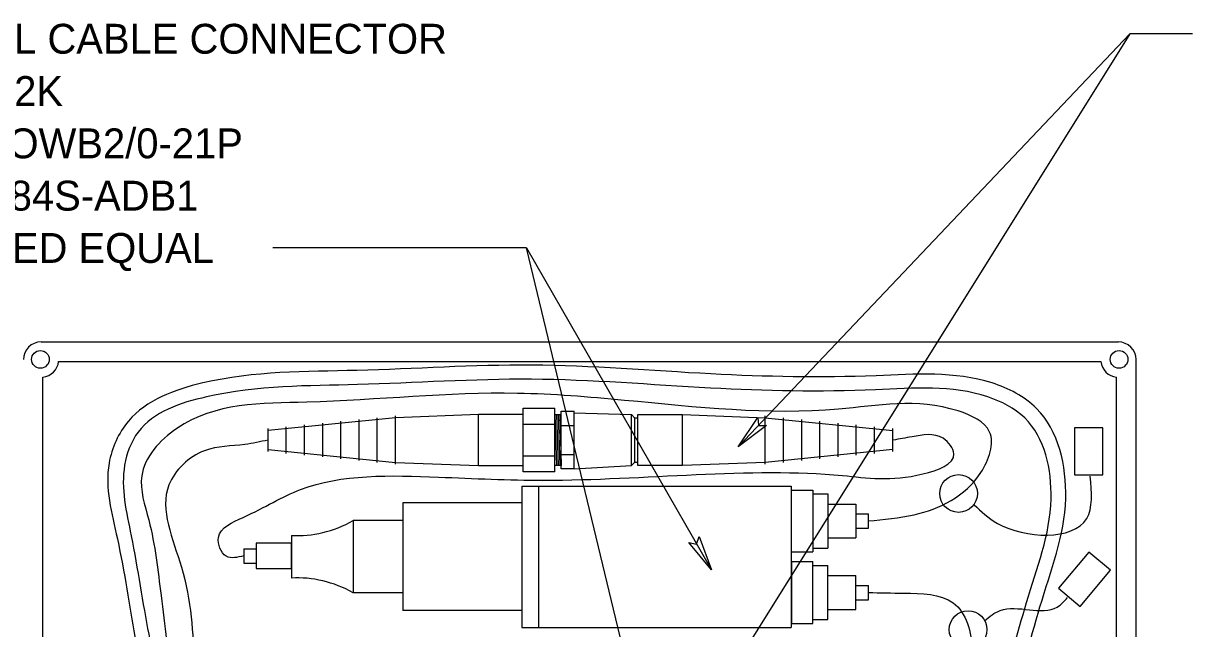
# Model space of a CAD drawing. Extents: x 99981 to 128681, y 99783 to 102182.
# Drawn here: x 126688.5 to 127158.2, y 100893.4 to 101136.4 of the extents above; entities that cross this region are included whole.
import ezdxf

# ---------------------------------------------------------------- set-up
doc = ezdxf.new("R2010")
doc.units = 0
doc.layers.add('Level 1', color=7, linetype='Continuous')

msp = doc.modelspace()

# ---------------------------------------------------------------- linework, layer by layer
at = {"layer": 'Level 1'}
for p, q in [((127132.95, 101132.19), (126975.04, 100879.69)), ((127132.95, 101132.19), (126975.64, 100966.34)), ((127158.2, 101132.19), (127132.95, 101132.19)), ((126890.59, 101046.26), (126788.77, 101046.26)), ((126890.59, 101046.26), (126964.89, 100917)), ((126942.15, 100832.29), (126890.59, 101046.26)), ((126695.6, 101008.52), (127128.39, 101008.52)), ((126702.66, 101000.71), (127121.34, 101000.71)), ((127135.49, 100721.17), (127135.49, 101001.42)), ((126696.31, 100728.23), (126696.31, 100994.36)), ((127127.69, 100728.23), (127127.69, 100994.36)), ((126889.22, 100956.32), (126889.22, 100981.92)), ((126889.22, 100981.92), (126902.03, 100981.92)), ((126902.03, 100956.32), (126902.03, 100981.92)), ((126904.59, 100957.62), (126904.59, 100980.66)), ((126904.59, 100980.66), (126909.71, 100980.66)), ((126909.71, 100957.62), (126909.71, 100980.66)), ((126909.71, 100980.02), (126932.75, 100979.36)), ((126838.02, 100978.08), (126786.81, 100972.96)), ((126801.43, 100963.05), (126801.43, 100975.19)), ((126808.75, 100962.31), (126808.75, 100975.93)), ((126816.05, 100961.59), (126816.05, 100976.64)), ((126823.37, 100960.85), (126823.37, 100977.39)), ((126830.69, 100960.13), (126830.69, 100978.1)), ((126871.3, 100979.33), (126838.02, 100978.08)), ((126838.02, 100959.39), (126838.02, 100978.85)), ((126889.22, 100979.36), (126871.3, 100979.33)), ((126871.3, 100958.85), (126871.3, 100979.33)), ((126889.22, 100975.52), (126902.03, 100975.52)), ((126902.03, 100979.38), (126904.59, 100979.38)), ((126902.03, 100979.38), (126902.67, 100958.9)), ((126902.67, 100979.38), (126903.31, 100958.9)), ((126903.31, 100979.38), (126903.95, 100958.9)), ((126903.95, 100979.38), (126904.59, 100958.9)), ((126932.75, 100958.88), (126932.75, 100979.36)), ((126934.01, 100978.1), (126932.75, 100979.36)), ((126934.01, 100978.1), (126935.31, 100978.1)), ((126934.01, 100978.1), (126934.03, 100960.16)), ((126935.31, 100958.88), (126935.31, 100979.36)), ((126935.31, 100979.36), (126953.23, 100979.33)), ((126953.23, 100958.85), (126953.23, 100979.33)), ((126953.23, 100979.33), (126986.52, 100978.08)), ((126986.52, 100959.39), (126986.52, 100978.85)), ((126986.52, 100978.08), (127037.73, 100972.96)), ((126993.84, 100960.13), (126993.84, 100978.1)), ((127001.17, 100960.85), (127001.17, 100977.39)), ((127008.49, 100961.59), (127008.49, 100976.64)), ((127015.79, 100962.31), (127015.79, 100975.93)), ((127023.11, 100963.05), (127023.11, 100975.19)), ((126786.81, 100964.51), (126786.81, 100973.73)), ((126794.1, 100963.77), (126794.1, 100974.44)), ((126904.59, 100974.9), (126909.71, 100974.9)), ((127030.43, 100963.77), (127030.43, 100974.44)), ((127037.73, 100964.51), (127037.73, 100973.73)), ((126786.81, 100965.28), (126838.02, 100960.16)), ((126889.22, 100962.72), (126902.03, 100962.72)), ((126904.59, 100963.38), (126909.71, 100963.38)), ((127037.73, 100965.28), (126986.52, 100960.16)), ((126838.02, 100960.16), (126871.3, 100958.85)), ((126871.3, 100958.85), (126889.22, 100958.88)), ((126904.59, 100958.9), (126902.03, 100958.9)), ((126909.71, 100957.62), (126904.59, 100957.62)), ((126909.71, 100957.62), (126932.75, 100958.88)), ((126932.75, 100958.88), (126934.03, 100960.16)), ((126935.31, 100960.16), (126934.03, 100960.16)), ((126953.23, 100958.85), (126935.31, 100958.88)), ((126986.52, 100960.16), (126953.23, 100958.85)), ((126902.03, 100956.32), (126889.22, 100956.32)), ((126888.78, 100950.64), (126996.96, 100950.64)), ((126888.78, 100950.64), (126888.78, 100893.88)), ((126895.38, 100950.64), (126895.38, 100893.88)), ((126996.96, 100950.64), (126996.96, 100893.88)), ((126997.06, 100949.05), (127005.66, 100949.05)), ((126997.06, 100924.21), (126997.06, 100949.05)), ((127005.66, 100949.05), (127005.66, 100924.21)), ((127005.66, 100947.5), (127011.68, 100947.5)), ((127011.68, 100947.5), (127011.68, 100925.76)), ((126888.78, 100943.86), (126840.87, 100943.86)), ((126840.87, 100943.86), (126840.87, 100900.66)), ((126888.78, 100943.86), (126888.78, 100900.66)), ((127011.68, 100943.42), (127022.95, 100943.42)), ((127022.95, 100943.42), (127022.95, 100929.84)), ((127022.95, 100939.5), (127027.96, 100939.5)), ((127027.96, 100933.76), (127027.96, 100939.5)), ((126821, 100936.76), (126821, 100907.76)), ((126840.87, 100936.76), (126821, 100936.76)), ((127022.95, 100933.76), (127027.96, 100933.76)), ((126796.17, 100930.82), (126796.17, 100913.69)), ((127011.68, 100929.84), (127022.95, 100929.84)), ((126777.03, 100925.47), (126782.04, 100925.47)), ((126777.03, 100925.47), (126777.03, 100919.73)), ((126997.06, 100924.21), (127005.66, 100924.21)), ((127005.66, 100925.76), (127011.68, 100925.76)), ((126777.03, 100919.73), (126782.04, 100919.73)), ((126997.06, 100920.3), (127005.66, 100920.3)), ((126997.06, 100920.3), (126997.06, 100895.46)), ((127005.66, 100895.46), (127005.66, 100920.3)), ((127005.66, 100918.75), (127011.68, 100918.75)), ((127011.68, 100897.01), (127011.68, 100918.75)), ((127011.68, 100914.67), (127022.95, 100914.67)), ((127022.95, 100901.09), (127022.95, 100914.67)), ((127022.95, 100910.75), (127027.96, 100910.75)), ((127027.96, 100905.01), (127027.96, 100910.75)), ((126840.87, 100907.76), (126821, 100907.76)), ((127022.95, 100905.01), (127027.96, 100905.01)), ((126888.78, 100900.66), (126840.87, 100900.66)), ((127011.68, 100901.09), (127022.95, 100901.09)), ((126997.06, 100895.46), (127005.66, 100895.46)), ((127005.66, 100897.01), (127011.68, 100897.01)), ((126888.78, 100893.88), (126996.96, 100893.88))]:
    msp.add_line(p, q, dxfattribs=at)
for points in [[(126987.08, 100974.92), (126975.64, 100966.34), (126983.6, 100978.22), (126983.82, 100974.96)], [(127122.17, 100955.11), (127122.17, 100974.03), (127110.82, 100974.03), (127110.82, 100955.11)], [(126959.94, 100930.42), (126964.89, 100917), (126955.79, 100928.03), (126958.97, 100927.31)], [(126782, 100917.55), (126796.25, 100917.55), (126796.25, 100927.65), (126782, 100927.65)], [(127113.06, 100902.33), (127125.22, 100916.82), (127116.52, 100924.12), (127104.36, 100909.63)]]:
    msp.add_lwpolyline(points, close=True, dxfattribs=at)
for centre, radius in [((126695.34, 101001.5), 3.55), ((127128.66, 101001.5), 3.55), ((127064.18, 100947.65), 7.57), ((127068, 100893.02), 7.57)]:
    msp.add_circle(centre, radius, dxfattribs=at)
for centre, start, end in [((126695.6, 101001.42), 90, 180), ((127128.4, 101001.42), 0, 90), ((126695.6, 101001.42), 276.1552, 354.2608), ((127128.4, 101001.42), 185.7392, 264.2608)]:
    msp.add_arc(centre, 7.09, start, end, dxfattribs=at)
for centre, major_axis, start_param, end_param in [((126798.65, 101032.14), (0, -101.39), 6.245521, 6.629239), ((126798.65, 100812.38), (0, 101.39), 5.937131, 6.32085)]:
    msp.add_ellipse(centre, major_axis=major_axis, ratio=0.64994, start_param=start_param, end_param=end_param, dxfattribs=at)
for points in [[(127028.7, 100842.7), (127043.81, 100844.68), (127081.11, 100863.74), (127096.88, 100902.1), (127107.23, 100945.75), (127095.48, 100981.83), (127077.62, 100992.04), (127031.02, 100994.96), (126964.69, 100995.67), (126892.64, 100999.2), (126822.45, 100997.07), (126760.53, 100992.03), (126730.71, 100976.71), (126722.94, 100959.9), (126726.25, 100929.46), (126733.23, 100890.29), (126737.45, 100870.11), (126736.48, 100847.55), (126734.69, 100847.35)], [(127027.96, 100848.33), (127042.1, 100850.18), (127076.66, 100867.84), (127091.46, 100903.85), (127101.34, 100945.51), (127090.76, 100977.99), (127075.95, 100986.46), (127030.82, 100989.29), (126964.52, 100989.99), (126892.59, 100993.52), (126822.77, 100991.4), (126762.12, 100986.46), (126734.62, 100972.34), (126729.19, 100959.09), (126731.8, 100930.68), (126738.85, 100891.14), (126743.65, 100864.09), (126739.33, 100843.02), (126735.32, 100841.71)], [(127027.96, 100936.63), (127046.33, 100939.15), (127073.13, 100956.1), (127076.66, 100972.34), (127063.96, 100980.81), (127016.01, 100981.52), (126929.97, 100985.05), (126886.95, 100987.87), (126802.32, 100984.34), (126750.13, 100973.75), (126736.03, 100954.69), (126738.85, 100937.03), (126743.79, 100906.67), (126748.02, 100870.66), (126749.43, 100849.48), (126748.02, 100831.82), (126740.26, 100821.94), (126735.32, 100822.64)], [(126777.03, 100922.6), (126769.99, 100922.49), (126766.88, 100929.96), (126776.83, 100938.05), (126799.84, 100949.26), (126855.2, 100954.25), (126897.49, 100953), (127017.52, 100954.87), (127049.86, 100955.49), (127062.3, 100963.59), (127057.95, 100969.81), (127045.51, 100970.44), (127037.86, 100969.11)], [(126786.81, 100969.12), (126777.46, 100967.32), (126761.29, 100964.83), (126746.98, 100951.13), (126751.96, 100918.13), (126760.04, 100839.04), (126773.78, 100808.1), (126797.98, 100794.83), (126858.93, 100791.1), (126908.68, 100786.11), (126924.41, 100780.11)], [(127070.44, 100943.13), (127079.79, 100935.65), (127115.65, 100937.56), (127117.04, 100954.61)], [(127027.96, 100907.88), (127042.29, 100907.62), (127062, 100903.76), (127069.29, 100884.45), (127065.86, 100854.42), (127075.72, 100845.83), (127088.57, 100845.4)], [(127074.61, 100896.5), (127080.87, 100900.68), (127103.82, 100902.07), (127108, 100905.89)]]:
    msp.add_spline(points, degree=3, dxfattribs=at)

# ---------------------------------------------------------------- texts
for s, p in [('MECHANICAL CABLE CONNECTOR', (126588.5, 101124.26)), ('HOMAC 3L3-2K', (126588.5, 101103.26)), ('POLARIS SLOWB2/0-21P', (126588.5, 101082.26)), ('BUCHANAN 84S-ADB1', (126588.5, 101061.26)), ('OR APPROVED EQUAL ', (126588.5, 101040.26))]:
    msp.add_text(s, height=12, dxfattribs=at).set_placement(p)

doc.saveas('drawing.dxf')
